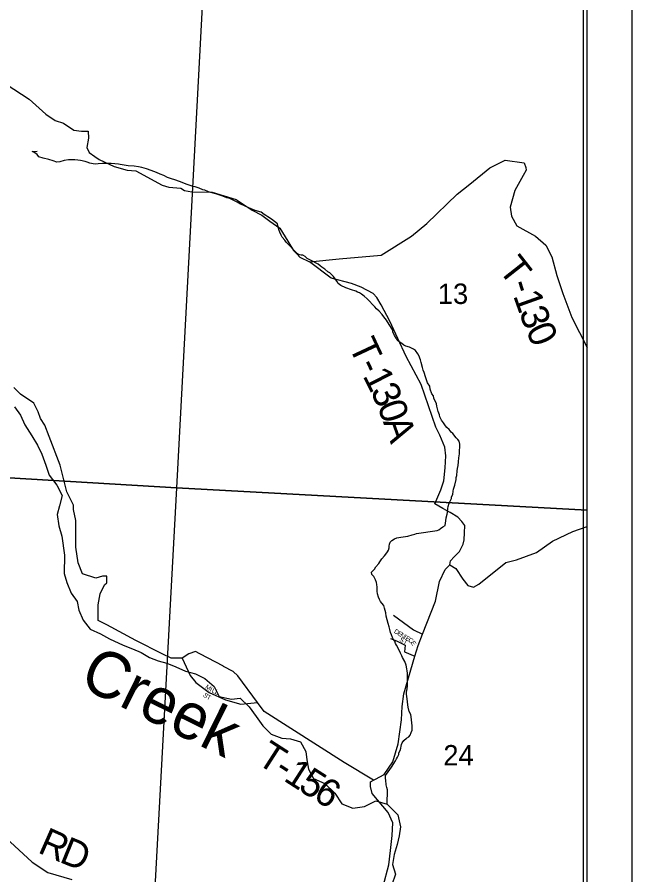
# Model space of a CAD drawing. Extents: x 0 to 34, y 0 to 22.
# Drawn here: x 7.74 to 9, y 18.037 to 19.794 of the extents above; entities that cross this region are included whole.
import ezdxf

# ---------------------------------------------------------------- set-up
doc = ezdxf.new("R2010")
doc.units = 0
for name, color, linetype in [('GM_X_County', 7, 'Continuous'), ('GM_X_County_Road', 7, 'Continuous'), ('GM_X_County_Road_Text', 7, 'Continuous'), ('GM_X_Minor_River', 7, 'Continuous'), ('GM_X_Minor_River_Text', 7, 'Continuous'), ('GM_X_Section', 7, 'Continuous'), ('GM_X_Section_Text', 7, 'Continuous'), ('GM_X_Township', 7, 'Continuous'), ('GM_X_Township_Road', 7, 'Continuous'), ('GM_X_Township_Road_Text', 7, 'Continuous'), ('GM_X_Township_ROW', 7, 'Continuous'), ('GM_X_Township_Subdivision', 7, 'Continuous'), ('GM_X_Township_Subdivision_Text', 7, 'Continuous'), ('SH_Data', 7, 'Continuous')]:
    doc.layers.add(name, color=color, linetype=linetype)

msp = doc.modelspace()

# ---------------------------------------------------------------- linework, layer by layer
at = {"layer": 'GM_X_County'}
msp.add_lwpolyline([(8.9084, 15.63), (8.9084, 20.8908), (2.1084, 20.8908), (2.1084, 19.9847)], dxfattribs=at)
at = {"layer": 'GM_X_County_Road'}
for points in [[(8.6198, 18.6652), (8.6198, 18.6652), (8.6268, 18.6722), (8.6391, 18.6644), (8.6536, 18.6423), (8.664, 18.6298), (8.6757, 18.6264), (8.6861, 18.6326), (8.742, 18.6768), (8.7636, 18.6825), (8.8045, 18.697), (8.8371, 18.7206), (8.8791, 18.7401), (8.9084, 18.7503)], [(8.4905, 18.0135), (8.5019, 18.0573), (8.5051, 18.0865), (8.5084, 18.1174), (8.51, 18.1433), (8.5003, 18.1644), (8.4678, 18.2034), (8.4646, 18.218), (8.4646, 18.2277), (8.4702, 18.2305), (8.4743, 18.2326), (8.4922, 18.2423), (8.51, 18.2683), (8.5213, 18.3056), (8.5278, 18.3543), (8.5295, 18.3818), (8.5327, 18.4078), (8.5553, 18.4846), (8.5619, 18.5068), (8.571, 18.53), (8.5976, 18.5976), (8.6057, 18.6381), (8.617, 18.6624), (8.6198, 18.6652)], [(7.6892, 18.1373), (7.7707, 18.0629), (7.8026, 18.0416), (7.8521, 18.0274)]]:
    msp.add_lwpolyline(points, dxfattribs=at)
at = {"layer": 'GM_X_Minor_River'}
for points in [[(8.3919, 19.2579), (8.3886, 19.2629), (8.3848, 19.2664), (8.3811, 19.2703), (8.377, 19.2726), (8.3707, 19.2776), (8.3643, 19.2819), (8.3609, 19.2846), (8.3568, 19.2881), (8.3426, 19.2956), (8.3347, 19.2999), (8.3306, 19.3034), (8.3257, 19.3061), (8.3223, 19.3066), (8.3189, 19.3074), (8.314, 19.3097), (8.3084, 19.3155), (8.304, 19.3205), (8.2991, 19.3252), (8.2958, 19.3287), (8.2913, 19.3333), (8.2884, 19.3371), (8.2832, 19.3433), (8.281, 19.3475), (8.2784, 19.3533), (8.277, 19.3571), (8.2756, 19.362), (8.2738, 19.3704), (8.2615, 19.3801), (8.254, 19.3848), (8.2495, 19.3879), (8.2461, 19.3895), (8.2401, 19.3942), (8.2277, 19.3982), (8.2146, 19.4037), (8.2048, 19.4081), (8.198, 19.4112), (8.1909, 19.4151), (8.1826, 19.4191), (8.1759, 19.4222), (8.1698, 19.4242), (8.1597, 19.4282), (8.1469, 19.4322), (8.1344, 19.4358), (8.1311, 19.437), (8.1247, 19.4394), (8.1209, 19.4406), (8.113, 19.4438), (8.1047, 19.4462), (8.1005, 19.447), (8.0945, 19.449), (8.0885, 19.4514), (8.0727, 19.457), (8.0633, 19.4606), (8.0561, 19.463), (8.0479, 19.4658), (8.0403, 19.4693), (8.0332, 19.4725), (8.0253, 19.4757), (8.0144, 19.48), (8.005, 19.4832), (7.9956, 19.486), (7.9922, 19.4865), (7.9888, 19.4877), (7.9801, 19.4886), (7.9676, 19.4895), (7.9593, 19.4908), (7.9514, 19.4921), (7.948, 19.4929), (7.9328, 19.4943), (7.915, 19.4942), (7.9063, 19.4932), (7.9006, 19.493), (7.8961, 19.4934), (7.8889, 19.4947), (7.8836, 19.4967), (7.8791, 19.4986), (7.8697, 19.5003), (7.864, 19.5012), (7.8583, 19.5017), (7.8523, 19.5018), (7.8455, 19.5015), (7.8364, 19.5001), (7.8272, 19.4976), (7.8211, 19.4966), (7.8136, 19.4994), (7.8046, 19.5022), (7.7933, 19.505), (7.7842, 19.5082), (7.7813, 19.5128), (7.7742, 19.5175), (7.7704, 19.5191), (7.781, 19.5193)], [(8.6009, 18.7422), (8.604, 18.7439), (8.6079, 18.7461), (8.6125, 18.7499), (8.6171, 18.7528), (8.6187, 18.7623), (8.6192, 18.768), (8.6213, 18.7759), (8.6221, 18.7793), (8.6226, 18.7873), (8.6238, 18.7918), (8.6258, 18.7982), (8.6302, 18.808), (8.6306, 18.8115), (8.6329, 18.816), (8.6338, 18.8228), (8.6347, 18.8273), (8.6371, 18.8349), (8.6399, 18.847), (8.64, 18.8512), (8.6412, 18.8553), (8.6421, 18.8648), (8.6426, 18.8694), (8.6438, 18.8754), (8.6447, 18.883), (8.6456, 18.8909), (8.6465, 18.8997), (8.6467, 18.9057), (8.6472, 18.9137), (8.6473, 18.9194), (8.6462, 18.9251), (8.6433, 18.929), (8.6399, 18.9324), (8.6333, 18.9409), (8.6299, 18.944), (8.6254, 18.949), (8.621, 18.9536), (8.618, 18.9571), (8.6139, 18.9629), (8.6095, 18.9687), (8.6066, 18.9755), (8.6059, 18.9793), (8.603, 18.9859), (8.6002, 18.9969), (8.5995, 19.0015), (8.5944, 19.0137), (8.5933, 19.0179), (8.59, 19.0222), (8.5868, 19.0317), (8.5857, 19.0378), (8.5809, 19.0451), (8.577, 19.0573), (8.5745, 19.0657), (8.5723, 19.0707), (8.5709, 19.076), (8.5684, 19.0863), (8.567, 19.092), (8.5655, 19.0955), (8.5637, 19.0997), (8.5611, 19.1043), (8.5567, 19.1108), (8.5526, 19.1135), (8.5481, 19.1159), (8.544, 19.1179), (8.5364, 19.1203), (8.5327, 19.1222), (8.5282, 19.1254), (8.5229, 19.1289), (8.5192, 19.1323), (8.5166, 19.1366), (8.5137, 19.1419), (8.51, 19.1492), (8.5097, 19.1526), (8.5027, 19.1641), (8.4972, 19.173), (8.4913, 19.1803), (8.4879, 19.1849), (8.482, 19.1915), (8.4768, 19.1965), (8.4731, 19.2003), (8.4682, 19.205), (8.4619, 19.2123), (8.4575, 19.2169), (8.4515, 19.2223), (8.4455, 19.2266), (8.4418, 19.2293), (8.4376, 19.2309), (8.4339, 19.2329), (8.4256, 19.2353), (8.4135, 19.2397), (8.4034, 19.2444), (8.3978, 19.2487), (8.3952, 19.2533), (8.3919, 19.2579)], [(7.7342, 18.9958), (7.747, 18.9783), (7.756, 18.9585), (7.7703, 18.9364), (7.7816, 18.9174), (7.7906, 18.8984), (7.7988, 18.8763), (7.8055, 18.8558), (7.8213, 18.8352), (7.8319, 18.814), (7.8265, 18.7927), (7.8219, 18.7753), (7.8255, 18.7517), (7.8315, 18.7304), (7.8367, 18.6917), (7.8365, 18.6545), (7.8417, 18.6355), (7.8507, 18.6142), (7.8628, 18.5967), (7.8665, 18.5792), (7.8755, 18.5587), (7.8898, 18.5404), (7.911, 18.5304), (7.9291, 18.5205), (7.9571, 18.5075), (7.9767, 18.4998), (7.9941, 18.4922), (8.0115, 18.4822), (8.0289, 18.4753), (8.047, 18.4707), (8.0652, 18.463), (8.0848, 18.4539), (8.1053, 18.4485), (8.1249, 18.4393), (8.1438, 18.4225), (8.1543, 18.402), (8.1793, 18.3965), (8.1974, 18.3988), (8.2155, 18.3812), (8.2299, 18.3614), (8.2434, 18.3424), (8.2608, 18.3248), (8.2827, 18.3172), (8.3001, 18.3156), (8.3205, 18.3094), (8.3318, 18.2896), (8.334, 18.2722), (8.337, 18.2532), (8.3475, 18.2341), (8.3709, 18.2242), (8.3913, 18.2043), (8.4056, 18.1823), (8.4283, 18.1738), (8.4518, 18.1768), (8.4753, 18.1888), (8.4987, 18.1819), (8.5206, 18.1598), (8.5258, 18.1355), (8.5227, 18.1165), (8.5188, 18.099), (8.5127, 18.0785), (8.5096, 18.058), (8.5156, 18.0382), (8.5079, 18.0162)], [(8.4987, 18.1819), (8.4992, 18.2112), (8.4978, 18.2158), (8.4964, 18.2215), (8.4954, 18.2306), (8.4947, 18.2345), (8.4952, 18.2405), (8.5006, 18.2477), (8.5041, 18.2529), (8.5072, 18.2578), (8.5123, 18.2649), (8.5154, 18.2702), (8.5178, 18.2747), (8.5193, 18.2781), (8.5221, 18.2834), (8.5225, 18.2868), (8.5252, 18.2913), (8.5265, 18.2962), (8.5273, 18.3004), (8.5281, 18.3038), (8.5293, 18.3076), (8.5328, 18.3121), (8.5378, 18.3166), (8.5428, 18.3199), (8.5459, 18.3233), (8.5475, 18.3286), (8.5495, 18.3331), (8.5496, 18.3426), (8.5493, 18.3475), (8.5483, 18.3551), (8.5466, 18.3654), (8.5433, 18.3712), (8.5416, 18.3803), (8.5409, 18.3853), (8.5399, 18.391), (8.5396, 18.3975), (8.5383, 18.407), (8.5383, 18.4112), (8.5396, 18.418), (8.5401, 18.4244), (8.5404, 18.4453), (8.5402, 18.4503), (8.5391, 18.4548), (8.5388, 18.459), (8.5374, 18.4663), (8.5345, 18.4739), (8.5301, 18.482), (8.5287, 18.4854), (8.5257, 18.4911), (8.5239, 18.4957), (8.5173, 18.5076), (8.5158, 18.5111), (8.514, 18.5157), (8.5114, 18.5191), (8.5096, 18.5233), (8.5074, 18.5287), (8.5056, 18.5337), (8.5038, 18.5394), (8.5024, 18.5447), (8.5003, 18.5516), (8.4985, 18.5592), (8.4967, 18.5665), (8.4957, 18.5737), (8.4933, 18.5832), (8.4915, 18.5886), (8.4877, 18.5932), (8.4848, 18.5971), (8.4826, 18.6009), (8.4808, 18.6055), (8.4786, 18.6124), (8.478, 18.6181), (8.4777, 18.6264), (8.4774, 18.6314), (8.4768, 18.6356), (8.4746, 18.6413), (8.4713, 18.6482), (8.4668, 18.6524), (8.4665, 18.657), (8.4723, 18.6634), (8.4754, 18.6679), (8.4816, 18.675), (8.4832, 18.6784), (8.4878, 18.6844), (8.4929, 18.6904), (8.4956, 18.6941), (8.4991, 18.6986), (8.501, 18.702), (8.5022, 18.7065), (8.5027, 18.7099), (8.5035, 18.7141), (8.5047, 18.7183), (8.5078, 18.722), (8.5136, 18.7253), (8.5181, 18.7272), (8.5261, 18.7289), (8.5311, 18.7296), (8.5405, 18.731), (8.5497, 18.7335), (8.555, 18.7349), (8.5588, 18.736), (8.6009, 18.7422)]]:
    msp.add_lwpolyline(points, dxfattribs=at)
at = {"layer": 'GM_X_Section'}
for p, q in [((8.9084, 18.7841), (8.9084, 19.8145)), ((8.9084, 17.7699), (8.9084, 18.7841))]:
    msp.add_line(p, q, dxfattribs=at)
for points in [[(8.1212, 19.8553), (8.0664, 18.8297), (6.9681, 18.8952), (7.0324, 19.92)], [(6.9681, 18.8952), (8.0664, 18.8297), (8.012, 17.8219), (6.9079, 17.8893)]]:
    msp.add_lwpolyline(points, close=True, dxfattribs=at)
for points in [[(8.9084, 19.8145), (8.1212, 19.8553), (8.0664, 18.8297), (8.9084, 18.7841)], [(8.9084, 18.7841), (8.0664, 18.8297), (8.012, 17.8219), (8.9084, 17.7699)]]:
    msp.add_lwpolyline(points, dxfattribs=at)
at = {"layer": 'GM_X_Township'}
msp.add_lwpolyline([(8.9084, 15.63), (8.9084, 20.8908), (5.9855, 20.8908)], dxfattribs=at)
at = {"layer": 'GM_X_Township_Road'}
for points in [[(8.6676, 19.452), (8.7091, 19.4855), (8.7403, 19.5011), (8.7792, 19.4959), (8.7824, 19.4859), (8.7833, 19.4804), (8.7769, 19.4698), (8.7599, 19.439), (8.7505, 19.4049), (8.7532, 19.3863), (8.7639, 19.3666), (8.8026, 19.345), (8.8235, 19.3269), (8.8357, 19.303), (8.846, 19.2647), (8.8586, 19.2279), (8.8773, 19.1787), (8.9084, 19.1174)], [(8.5204, 19.1356), (8.5036, 19.1715), (8.486, 19.2046), (8.4773, 19.2194), (8.4696, 19.2278), (8.4454, 19.2406), (8.425, 19.2487), (8.3837, 19.2592), (8.339, 19.2927)], [(8.6268, 18.6722), (8.628, 18.6799), (8.6357, 18.6886), (8.6469, 18.6993), (8.6545, 18.7141), (8.6566, 18.7235), (8.6568, 18.7373), (8.6573, 18.7526), (8.6515, 18.7605), (8.6431, 18.7697), (8.6277, 18.7789), (8.6127, 18.7873), (8.5964, 18.797), (8.6086, 18.8256), (8.6147, 18.8439), (8.6173, 18.871), (8.6188, 18.895), (8.6163, 18.9128), (8.6061, 18.9378), (8.5979, 18.9541), (8.5678, 19.0414), (8.5377, 19.0988), (8.5204, 19.1356)], [(8.1629, 18.4641), (8.1147, 18.4898), (8.1056, 18.4944), (8.092, 18.4898), (8.0784, 18.4807), (8.0556, 18.4807), (8.0375, 18.4898), (7.9829, 18.5171), (7.9238, 18.5489), (7.9057, 18.558), (7.9057, 18.5898), (7.9102, 18.6125), (7.9193, 18.6307), (7.9238, 18.6353), (7.9238, 18.6489), (7.9148, 18.6489), (7.9011, 18.6444), (7.8738, 18.6534), (7.8648, 18.6762), (7.8602, 18.708), (7.8602, 18.7625), (7.8557, 18.7852), (7.8557, 18.7943), (7.842, 18.8216), (7.8284, 18.8761), (7.8057, 18.9352), (7.7966, 18.9579), (7.7875, 18.9716), (7.783, 18.9852), (7.7739, 19.0034), (7.7466, 19.0215), (7.733, 19.0352)], [(8.4702, 18.2305), (8.4101, 18.267), (8.2465, 18.3716), (8.2329, 18.3898), (8.192, 18.4444), (8.1829, 18.4535), (8.163, 18.464), (8.1629, 18.4641)]]:
    msp.add_lwpolyline(points, dxfattribs=at)
at = {"layer": 'GM_X_Township_ROW'}
msp.add_lwpolyline([(7.701, 19.6673), (7.7645, 19.6257), (7.7989, 19.5951), (7.8178, 19.5824), (7.8349, 19.5765), (7.8558, 19.5628), (7.8718, 19.5602), (7.8856, 19.5607), (7.8864, 19.5462), (7.8831, 19.527), (7.8874, 19.5166), (7.8989, 19.5084), (7.9081, 19.5026), (7.9387, 19.488), (7.9652, 19.4806), (7.983, 19.4791), (8.0371, 19.4498), (8.0511, 19.4454), (8.0756, 19.4439), (8.0833, 19.4388), (8.0981, 19.4362), (8.1394, 19.4352), (8.1888, 19.4204), (8.222, 19.3985), (8.2414, 19.3883), (8.2577, 19.376), (8.2786, 19.3618), (8.2949, 19.3352), (8.3062, 19.3158), (8.3141, 19.3082), (8.3194, 19.3026), (8.339, 19.2927), (8.4003, 19.2988), (8.4859, 19.3066), (8.5482, 19.3455), (8.5794, 19.3714), (8.6417, 19.4311), (8.6676, 19.452)], dxfattribs=at)
at = {"layer": 'GM_X_Township_Subdivision'}
for points in [[(8.5114, 18.5686), (8.5522, 18.5388), (8.571, 18.53)], [(8.5055, 18.5212), (8.5177, 18.5161), (8.5351, 18.5076), (8.5338, 18.4937), (8.5553, 18.4846)], [(8.0784, 18.4807), (8.0948, 18.4454), (8.1059, 18.4306), (8.1336, 18.4103), (8.1669, 18.3955), (8.1984, 18.3862), (8.2329, 18.3898)]]:
    msp.add_lwpolyline(points, dxfattribs=at)
at = {"layer": 'SH_Data'}
for p, q in [((9, 21), (9, 14)), ((8.9, 20.9), (8.9, 14.1))]:
    msp.add_line(p, q, dxfattribs=at)

# ---------------------------------------------------------------- texts
at = {"layer": 'GM_X_County_Road_Text'}
for s, rotation, p in [('R', 336.144, (7.7801, 18.0835)), ('D', 337.8426, (7.8244, 18.0639))]:
    msp.add_text(s, height=0.0568, rotation=rotation, dxfattribs=at).set_placement(p)
at = {"layer": 'GM_X_Minor_River_Text'}
msp.add_text('Creek', height=0.0947, rotation=333.7756, dxfattribs=at).set_placement((7.8635, 18.4249))
at = {"layer": 'GM_X_Section_Text'}
for s, p in [('13', (8.6023, 19.2064)), ('24', (8.6135, 18.2609))]:
    msp.add_text(s, height=0.04186, rotation=0, dxfattribs=at).set_placement(p)
at = {"layer": 'GM_X_Township_Road_Text'}
for s, rotation, p in [('T', 308.206, (8.7247, 19.2769)), ('-', 287.3509, (8.7484, 19.2483)), ('1', 289.5887, (8.7562, 19.2237)), ('3', 290.0178, (8.7681, 19.1903)), ('0', 293.9829, (8.7816, 19.1534)), ('T', 295.0707, (8.4187, 19.1206)), ('-', 295.5066, (8.4369, 19.0816)), ('1', 296.7734, (8.4475, 19.0594)), ('3', 295.2817, (8.4631, 19.0285)), ('0', 289.9467, (8.4775, 18.9981)), ('A', 289.6227, (8.4894, 18.9653)), ('T', 327.265, (8.2285, 18.2668)), ('-', 327.2813, (8.2643, 18.2438)), ('1', 327.3352, (8.284, 18.2311)), ('5', 327.5691, (8.3137, 18.2121)), ('6', 328.6213, (8.3442, 18.1927))]:
    msp.add_text(s, height=0.0568, rotation=rotation, dxfattribs=at).set_placement(p)
at = {"layer": 'GM_X_Township_Subdivision_Text'}
for s, rotation, p in [('D', 328.7313, (8.5114, 18.5333)), ('E', 328.7158, (8.5185, 18.529)), ('ST', 330.2553, (8.5226, 18.516)), ('N', 328.7349, (8.5242, 18.5255)), ('I', 328.7223, (8.5313, 18.5212)), ('E', 328.7375, (8.5349, 18.5191)), ('C', 328.7181, (8.5406, 18.5156)), ('E', 303.154, (8.5462, 18.5125)), ('M', 325.0597, (8.1245, 18.4198)), ('I', 330.3156, (8.1335, 18.4135)), ('L', 335.5714, (8.1379, 18.411)), ('L', 338.1993, (8.1444, 18.4081)), ('S', 320.5311, (8.1201, 18.4035)), ('T', 334.6228, (8.1274, 18.3979))]:
    msp.add_text(s, height=0.00947, rotation=rotation, dxfattribs=at).set_placement(p)

doc.saveas('drawing.dxf')
